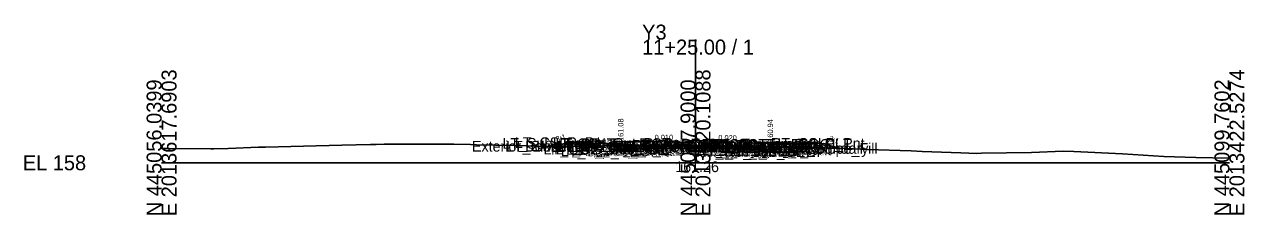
# Model space of a CAD drawing. Extents: x -26 to 203, y -10 to 5017.
# Drawn here: x -25.7 to 202.8, y 2490.3 to 2525.9 of the extents above; entities that cross this region are included whole.
import ezdxf

# ---------------------------------------------------------------- set-up
doc = ezdxf.new("R2010")
doc.units = 0
for name, color, linetype in [('Default', 7, 'Continuous'), ('Exist CMT Pavement', 7, 'Continuous'), ('Exist Cross Section Cell', 7, 'Continuous'), ('Exist XS Center Line Elevation Label', 7, 'Continuous'), ('Exist XS Ground Line', 7, 'Continuous'), ('Prop CMT Conc Surface', 7, 'Continuous'), ('Prop CMT Concrete Structures', 7, 'Continuous'), ('Prop CMT Pvmt Course 1', 7, 'Continuous'), ('Prop CMT Pvmt Course 1 CG', 7, 'Continuous'), ('Prop CMT Pvmt Course 1 Wedge', 7, 'Continuous'), ('Prop CMT Pvmt Course 2', 7, 'Continuous'), ('Prop CMT Pvmt Course 2 Wedge', 7, 'Continuous'), ('Prop CMT Pvmt Course 3', 7, 'Continuous'), ('Prop CMT Pvmt Course 3 Wedge', 7, 'Continuous'), ('Prop CMT Pvmt Surface', 7, 'Continuous'), ('Prop CMT Pvmt Wedge Surface 1', 7, 'Continuous'), ('Prop CMT Pvmt Wedge Surface 2', 7, 'Continuous'), ('Prop CMT Pvmt Wedge Surface 3', 7, 'Continuous'), ('Prop CMT Slope Grass', 7, 'Continuous'), ('Prop CMT Subgrade Earthwork', 7, 'Continuous'), ('Prop XS Earthwork Shape', 7, 'Continuous'), ('Prop XS Hydro Elevations', 7, 'Continuous'), ('Prop XS SE Text', 7, 'Continuous'), ('Prop XS Side Slope Text', 7, 'Continuous'), ('Scratch_Level_0', 7, 'Continuous')]:
    doc.layers.add(name, color=color, linetype=linetype)

msp = doc.modelspace()

# ---------------------------------------------------------------- linework, layer by layer
at = {"layer": 'Exist CMT Pavement'}
for points in [[(100, 2503.26), (100, 2503.26), (89, 2503)], [(100, 2503.26), (100.58, 2503.28), (111, 2502.93)]]:
    msp.add_lwpolyline(points, dxfattribs=at)
at = {"layer": 'Exist Cross Section Cell'}
for p, q in [((100, 2500), (100, 2523.06)), ((0, 2500), (100, 2500)), ((100, 2500), (200, 2500))]:
    msp.add_line(p, q, dxfattribs=at)
at = {"layer": 'Exist XS Ground Line'}
msp.add_lwpolyline([(0, 2502.69), (1.43, 2502.67), (9.21, 2502.59), (9.8, 2502.59), (12.44, 2502.69), (18.18, 2502.95), (19.46, 2502.95), (26.55, 2503.09), (33.74, 2503.3), (39.11, 2503.43), (40.2, 2503.45), (41.66, 2503.47), (43.17, 2503.47), (45.6, 2503.46), (50.39, 2503.46), (53.15, 2503.47), (54.71, 2503.46), (57.87, 2503.42), (58.99, 2503.38), (66.05, 2503.21), (72.7, 2503.08), (75.81, 2503.14), (78.11, 2503.13), (79.93, 2503.13), (82.84, 2503.18), (87.08, 2503.15), (87.56, 2503.13), (88.49, 2502.99), (100, 2503.26), (100.58, 2503.28), (102.91, 2503.2), (112.21, 2502.89), (113.51, 2503.07), (113.79, 2502.97), (116.59, 2502.9), (120.28, 2502.9), (128.2, 2502.66), (132.2, 2502.52), (140.36, 2502.21), (142.45, 2502.13), (149.69, 2501.87), (152.7, 2501.77), (153.57, 2501.79), (162.95, 2501.94), (168.89, 2502.16), (170.83, 2502.09), (179.98, 2501.68), (187.7, 2501.21), (193.69, 2501), (200, 2500.86)], dxfattribs=at)
at = {"layer": 'Prop CMT Conc Surface'}
for points in [[(86, 2503.08), (86, 2503.58), (85.5, 2503.58)], [(88, 2503.18), (86, 2503.08)], [(112, 2503.06), (114, 2502.94)], [(114, 2502.94), (114, 2503.44), (114.5, 2503.44)]]:
    msp.add_lwpolyline(points, dxfattribs=at)
at = {"layer": 'Prop CMT Concrete Structures'}
for points in [[(88, 2503.18), (86, 2503.08), (86, 2503.58), (85.5, 2503.58)], [(85.5, 2503.58), (85.5, 2502.57), (88, 2502.6)], [(88, 2502.6), (88, 2503.18)], [(112, 2503.06), (114, 2502.94), (114, 2503.44), (114.5, 2503.44)], [(114.5, 2503.44), (114.5, 2502.43), (112, 2502.48)], [(112, 2502.48), (112, 2503.06)]]:
    msp.add_lwpolyline(points, dxfattribs=at)
at = {"layer": 'Prop CMT Pvmt Course 1'}
for points in [[(100, 2503.3), (88, 2503.18)], [(88, 2503.18), (88, 2502.93)], [(88, 2502.93), (89, 2502.94)], [(89, 2503.07), (100, 2503.18)], [(89, 2502.94), (89, 2503.07)], [(100, 2503.05), (100, 2503.3)], [(100, 2503.3), (112, 2503.06)], [(100, 2503.05), (100, 2503.3)], [(100, 2503.18), (100, 2503.05), (100, 2503.05)], [(111, 2502.96), (100, 2503.18)], [(100, 2503.18), (100, 2503.05), (100, 2503.05)], [(111, 2502.83), (111, 2502.96)], [(112, 2502.81), (111, 2502.83)], [(112, 2503.06), (112, 2502.81)]]:
    msp.add_lwpolyline(points, dxfattribs=at)
at = {"layer": 'Prop CMT Pvmt Course 1 CG'}
for points in [[(88, 2502.6), (85, 2502.57), (84.66, 2502.23)], [(88, 2502.26), (88, 2502.6)], [(112, 2502.48), (115, 2502.42), (115.34, 2502.08)], [(112, 2502.14), (112, 2502.48)], [(84.66, 2502.23), (88, 2502.26)], [(115.34, 2502.08), (112, 2502.14)]]:
    msp.add_lwpolyline(points, dxfattribs=at)
at = {"layer": 'Prop CMT Pvmt Course 1 Wedge'}
for points in [[(100, 2503.18), (89, 2503.07)], [(100, 2503.18), (111, 2502.96)]]:
    msp.add_lwpolyline(points, dxfattribs=at)
at = {"layer": 'Prop CMT Pvmt Course 2'}
for points in [[(89, 2502.94), (88, 2502.93)], [(88, 2502.93), (88, 2502.6)], [(88, 2502.6), (89, 2502.61)], [(89, 2502.61), (89, 2502.94)], [(111, 2502.5), (111, 2502.83)], [(111, 2502.83), (112, 2502.81)], [(112, 2502.48), (111, 2502.5)], [(112, 2502.81), (112, 2502.48)]]:
    msp.add_lwpolyline(points, dxfattribs=at)
at = {"layer": 'Prop CMT Pvmt Course 2 Wedge'}
for points in [[(100, 2503.05), (89, 2502.94)], [(100, 2503.05), (111, 2502.83)]]:
    msp.add_lwpolyline(points, dxfattribs=at)
at = {"layer": 'Prop CMT Pvmt Course 3'}
for points in [[(89, 2502.61), (88, 2502.6)], [(88, 2502.6), (88, 2502.26)], [(89, 2502.27), (89, 2502.61)], [(111, 2502.5), (112, 2502.48)], [(111, 2502.16), (111, 2502.5)], [(112, 2502.48), (112, 2502.14)], [(88, 2502.26), (89, 2502.27)], [(112, 2502.14), (111, 2502.16)]]:
    msp.add_lwpolyline(points, dxfattribs=at)
at = {"layer": 'Prop CMT Pvmt Course 3 Wedge'}
for points in [[(100, 2502.72), (89, 2502.61)], [(100, 2502.72), (111, 2502.5)]]:
    msp.add_lwpolyline(points, dxfattribs=at)
at = {"layer": 'Prop CMT Pvmt Surface'}
for points in [[(100, 2503.3), (88, 2503.18)], [(100, 2503.3), (112, 2503.06)]]:
    msp.add_lwpolyline(points, dxfattribs=at)
at = {"layer": 'Prop CMT Pvmt Wedge Surface 1'}
for points in [[(88, 2502.93), (88, 2503.18)], [(89, 2502.94), (88, 2502.93)], [(100, 2503.18), (89, 2503.07)], [(89, 2503.07), (89, 2502.94)], [(100, 2503.18), (111, 2502.96)], [(111, 2502.96), (111, 2502.83)], [(111, 2502.83), (112, 2502.81)], [(112, 2502.81), (112, 2503.06)]]:
    msp.add_lwpolyline(points, dxfattribs=at)
at = {"layer": 'Prop CMT Pvmt Wedge Surface 2'}
for points in [[(88, 2502.93), (88, 2503.18)], [(100, 2503.05), (88, 2502.93)], [(100, 2503.05), (112, 2502.81)], [(112, 2502.81), (112, 2503.06)]]:
    msp.add_lwpolyline(points, dxfattribs=at)
at = {"layer": 'Prop CMT Pvmt Wedge Surface 3'}
for points in [[(88, 2502.6), (88, 2503.18)], [(100, 2502.72), (88, 2502.6)], [(100, 2502.72), (112, 2502.48)], [(112, 2502.48), (112, 2503.06)]]:
    msp.add_lwpolyline(points, dxfattribs=at)
at = {"layer": 'Prop CMT Slope Grass'}
for points in [[(85.5, 2503.58), (76, 2503.77), (74, 2503.11)], [(114.5, 2503.44), (124, 2503.63), (126.8, 2502.7)]]:
    msp.add_lwpolyline(points, dxfattribs=at)
at = {"layer": 'Prop CMT Subgrade Earthwork'}
for points in [[(88, 2502.26), (84.66, 2502.23), (83.27, 2503.63)], [(89, 2502.27), (89, 2503)], [(111, 2502.16), (111, 2502.93)], [(112, 2502.14), (115.34, 2502.08), (116.75, 2503.49)], [(89, 2502.27), (88, 2502.26)], [(111, 2502.16), (112, 2502.14)]]:
    msp.add_lwpolyline(points, dxfattribs=at)
at = {"layer": 'Prop XS Earthwork Shape'}
for points in [[(83.72, 2503.17), (83.27, 2503.63), (76, 2503.77), (74, 2503.11), (75.81, 2503.14), (78.11, 2503.13), (79.93, 2503.13), (82.84, 2503.18)], [(89, 2502.27), (89, 2503), (88.49, 2502.99), (88, 2503.06), (88, 2502.6), (85.5, 2502.57), (85.5, 2503.16), (83.72, 2503.17), (84.66, 2502.23), (88, 2502.26)], [(85.5, 2503.16), (85.5, 2502.57), (88, 2502.6), (88, 2503.06), (87.56, 2503.13), (87.23, 2503.14), (86, 2503.08), (86, 2503.16)], [(86, 2503.08), (86, 2503.16), (87.08, 2503.15), (87.23, 2503.14)], [(100.58, 2503.28), (111, 2502.93), (102.91, 2503.2)], [(115.34, 2502.08), (116.18, 2502.91), (114.5, 2502.95), (114.5, 2502.43), (112, 2502.48), (112, 2502.89), (111, 2502.93), (111, 2502.16), (112, 2502.14)], [(112, 2502.89), (112.21, 2502.89), (113.01, 2503), (114, 2502.94), (114, 2502.97), (114.5, 2502.95), (114.5, 2502.43), (112, 2502.48)], [(113.01, 2503), (114, 2502.94), (114, 2502.97), (113.79, 2502.97), (113.51, 2503.07)], [(116.75, 2503.49), (124, 2503.63), (126.8, 2502.7), (120.28, 2502.9), (116.59, 2502.9), (116.18, 2502.91)]]:
    msp.add_lwpolyline(points, close=True, dxfattribs=at)

# ---------------------------------------------------------------- texts
at = {"layer": 'Default'}
msp.add_text('-', height=0.0001, dxfattribs=at).set_placement((0, 2500))
at = {"layer": 'Exist Cross Section Cell'}
for s, p in [('Y3', (90, 2523.06)), ('11+25.00 / 1', (90, 2520.26)), ('EL 158', (-26, 2498.6))]:
    msp.add_text(s, height=2.8, dxfattribs=at).set_placement(p)
for s, p in [('E 2013617.6903', (2.8, 2490)), ('E 2013520.1088', (102.8, 2490)), ('E 2013422.5274', (202.8, 2490)), ('N 445056.0399', (0, 2490)), ('N 445077.9000', (100, 2490)), ('N 445099.7602', (200, 2490))]:
    msp.add_text(s, height=2.8, rotation=90, dxfattribs=at).set_placement(p)
at = {"layer": 'Exist XS Center Line Elevation Label'}
msp.add_text('161.26', height=2, dxfattribs=at).set_placement((96.21, 2498.26))
at = {"layer": 'Prop XS Hydro Elevations'}
for s, p in [('161.08', (86.5, 2504.08)), ('160.94', (114.5, 2503.94))]:
    msp.add_text(s, height=1, rotation=90, dxfattribs=at).set_placement(p)
at = {"layer": 'Prop XS SE Text'}
for s, rotation, p in [('0.010', 0.5729, (92.36, 2504.23)), ('0.020', 358.8542, (104.27, 2504.22))]:
    msp.add_text(s, height=1, rotation=rotation, dxfattribs=at).set_placement(p)
at = {"layer": 'Prop XS Side Slope Text'}
for rotation, p in [(18.4332, (74.01, 2503.9)), (341.5668, (124.9, 2504.12))]:
    msp.add_text('3:1', height=1, rotation=rotation, dxfattribs=at).set_placement(p)
at = {"layer": 'Scratch_Level_0'}
for s, p in [('LT_Sub_Trench_Out_DLT', (63.84, 2502.63)), ('LT_CSLP_Pnt', (66.17, 2502.77)), ('Exterior Boundary', (58.13, 2502.1)), ('LT_Slope_Fill', (64.51, 2502.1)), ('LT_CG1_Shelf_Out', (71.55, 2501.57)), ('LT_CG_Top_Face', (73.26, 2502.58)), ('LT_CG_Top_BOC', (73.78, 2502.58)), ('LT_CG_Bot_BOC', (73.81, 2501.57)), ('LT_PV_Sub_Tie_Out', (73.96, 2502)), ('LT_CG_Top_Gut', (74.24, 2502.08)), ('LT_Sub_OEOP', (74.77, 2501.23)), ('LT_PV_OEEOP_EG', (76.54, 2502)), ('LT_CG_Bot_IE', (77.91, 2501.6)), ('LT_Sub_OEOT', (78.08, 2501.26)), ('LT_PV2_OEOT', (78.17, 2501.93)), ('LT_PV3_OEOT', (78.17, 2501.6)), ('LT_Sub_OEEOP', (78.21, 2501.27)), ('LT_PV2_OEEOP', (78.31, 2501.94)), ('LT_PV3_OEEOP', (78.31, 2501.61)), ('LT_PV1_OEOT', (78.74, 2502.18)), ('LT_PV1_OEEOP', (78.87, 2502.07)), ('RT_PV_IEEOP_EG', (88.14, 2502.26)), ('LT_PV_IEEOP_EG', (88.19, 2502.26)), ('RT_PV2_IEEOP', (89.91, 2502.05)), ('RT_PV3_IEEOP', (89.91, 2501.72)), ('LT_PV2_IEEOP', (89.95, 2502.05)), ('LT_PV3_IEEOP', (89.95, 2501.72)), ('RT_PV1_IEEOP', (90.47, 2502.18)), ('LT_PV1_IEEOP', (90.52, 2502.18)), ('PV2_PGL', (93.91, 2502.05)), ('PV1_PGL', (94.47, 2502.3)), ('RT_PV_Sub_Tie_Out', (95.88, 2501.93)), ('RT_Sub_Trench_Out_DLT', (97.27, 2502.49)), ('RT_PV_OEEOP_EG', (98.5, 2501.93)), ('RT_Sub_OEEOP', (100.17, 2501.16)), ('RT_PV2_OEEOP', (100.26, 2501.83)), ('RT_PV3_OEEOP', (100.26, 2501.5)), ('RT_PV1_OEEOP', (100.83, 2501.96)), ('RT_CG_Top_Face', (101.21, 2502.44)), ('RT_CG1_Shelf_Out', (101.5, 2501.42)), ('RT_CG_Bot_IE', (101.87, 2501.48)), ('RT_Sub_OEOT', (102.03, 2501.14)), ('RT_PV2_OEOT', (102.13, 2501.81)), ('RT_PV3_OEOT', (102.13, 2501.48)), ('RT_CG_Top_Gut', (102.19, 2501.94)), ('RT_PV1_OEOT', (102.69, 2502.06)), ('RT_CG_Top_BOC', (102.74, 2502.44)), ('RT_CG_Bot_BOC', (102.77, 2501.43)), ('RT_Sub_OEOP', (105.4, 2501.08)), ('Exterior Boundary', (110.98, 2501.69)), ('RT_CSLP_Pnt', (114.13, 2502.63)), ('RT_Slope_Fill', (117.31, 2501.69))]:
    msp.add_text(s, height=2, dxfattribs=at).set_placement(p)

doc.saveas('drawing.dxf')
